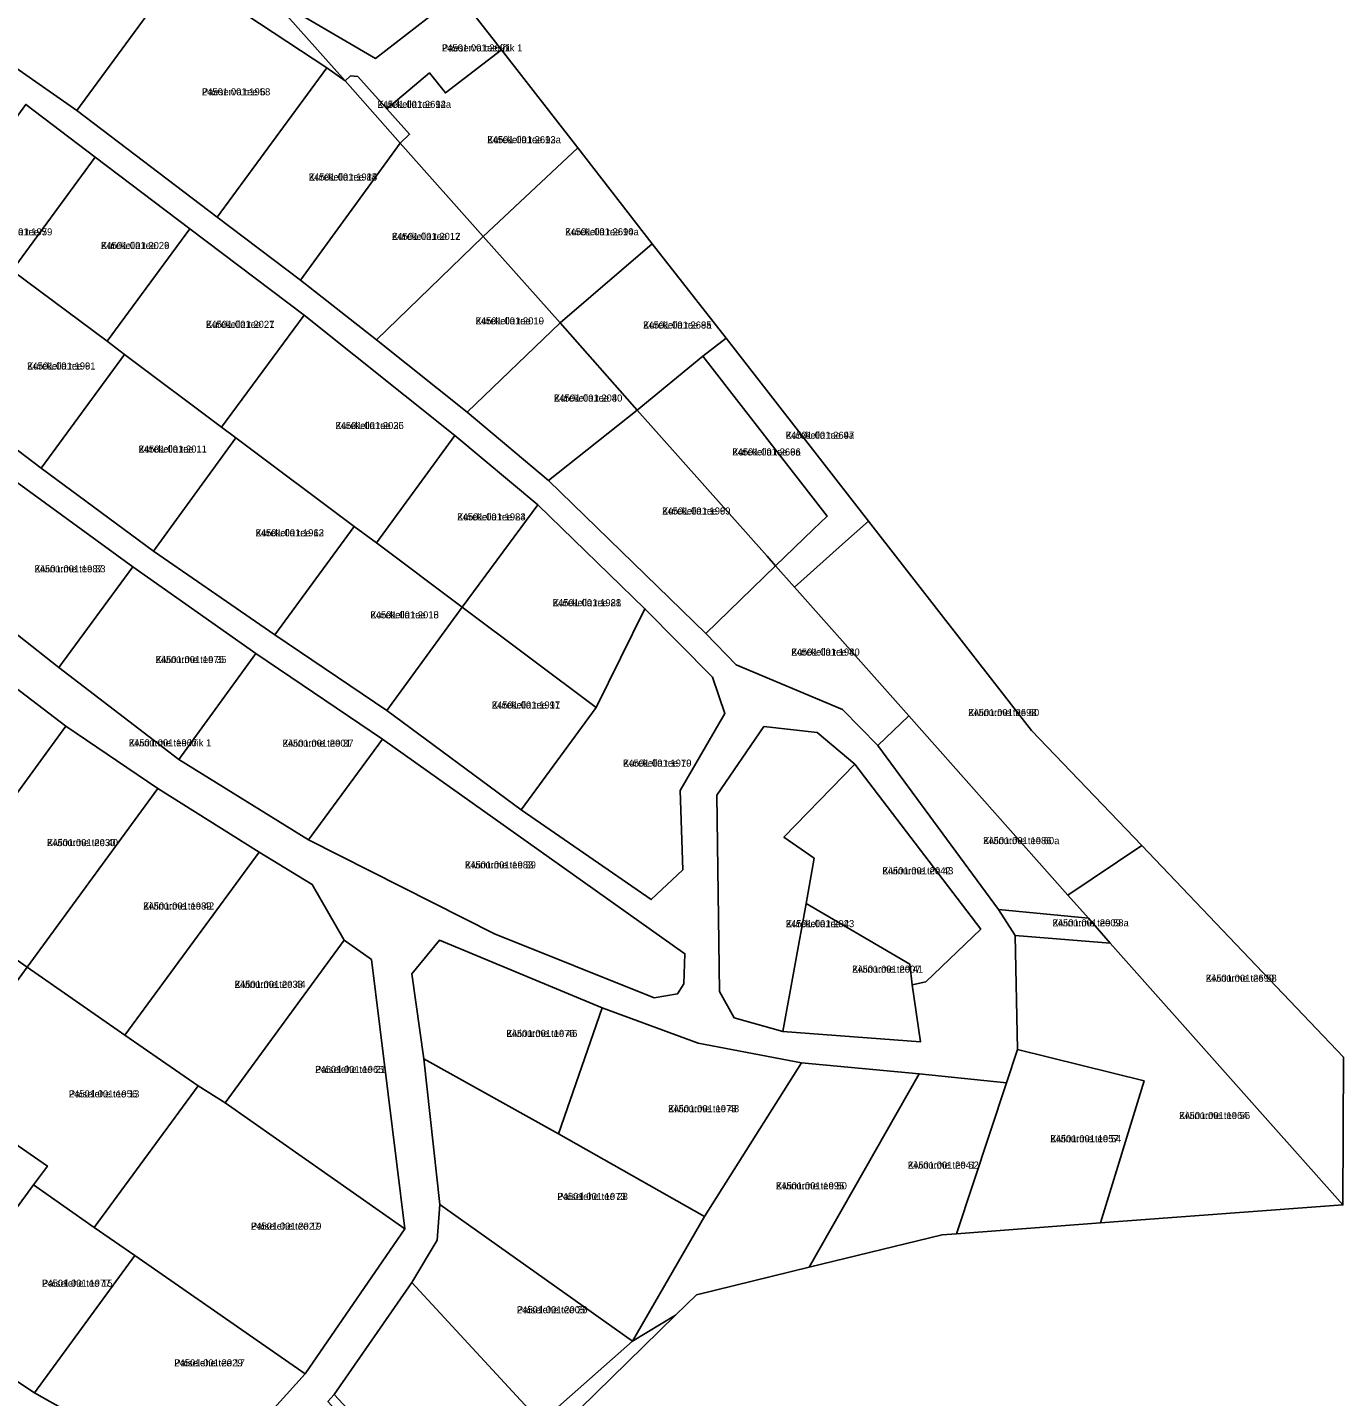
# Model space of a CAD drawing. Extents: x 551291 to 575799, y 6581704 to 6610137.
# Drawn here: x 559710.7 to 559989.7, y 6593302.2 to 6593592.3 of the extents above; entities that cross this region are included whole.
import ezdxf

# ---------------------------------------------------------------- set-up
doc = ezdxf.new("R2010")
doc.units = 0
for name, color, linetype in [('L_AADRESS', 7, 'Continuous'), ('PIIR', 7, 'Continuous'), ('TUNNUS', 7, 'Continuous')]:
    doc.layers.add(name, color=color, linetype=linetype)

msp = doc.modelspace()

# ---------------------------------------------------------------- linework, layer by layer
at = {"layer": 'PIIR'}
for points in [[(559693.82, 6593633.25), (559702.03, 6593640.34), (559704.01, 6593635.24), (559714.34, 6593627.36), (559736.46, 6593615.24), (559749.81, 6593606.84), (559762.28, 6593598.8), (559778.08, 6593580.98), (559774.19, 6593583.79), (559742.94, 6593604.41), (559719.13, 6593618), (559705.07, 6593624.88)], [(559752.19, 6593610.14), (559772.99, 6593640.46), (559802.82, 6593603.02), (559800.56, 6593601.2), (559802.05, 6593599.4), (559784.52, 6593585.74), (559762.28, 6593598.8)], [(559698.86, 6593590.33), (559719.13, 6593618), (559742.94, 6593604.41), (559721.24, 6593574.74)], [(559721.24, 6593574.74), (559742.94, 6593604.41), (559774.19, 6593583.79), (559750.95, 6593552.15)], [(559778.08, 6593580.98), (559762.28, 6593598.8), (559784.52, 6593585.74), (559802.05, 6593599.4), (559811.2, 6593587.6), (559799.32, 6593578.46), (559795.94, 6593582.69), (559786.91, 6593575.05), (559780.75, 6593581.92), (559779.19, 6593582.06)], [(559799.32, 6593578.46), (559811.2, 6593587.6), (559827.36, 6593566.82), (559807.35, 6593547.99), (559789.76, 6593567.8), (559791.74, 6593569.68), (559786.91, 6593575.05), (559795.94, 6593582.69)], [(559750.95, 6593552.15), (559774.19, 6593583.79), (559778.08, 6593580.98), (559789.76, 6593567.8), (559768.6, 6593538.79)], [(559789.76, 6593567.8), (559778.08, 6593580.98), (559779.19, 6593582.06), (559780.75, 6593581.92), (559786.91, 6593575.05), (559791.74, 6593569.68)], [(559692.59, 6593551.66), (559710.41, 6593576.02), (559725.11, 6593564.86), (559707.51, 6593540.85), (559690.02, 6593516.88), (559677.94, 6593526.12), (559695.35, 6593549.85)], [(559768.6, 6593538.79), (559789.76, 6593567.8), (559807.35, 6593547.99), (559784.72, 6593526.1)], [(559807.35, 6593547.99), (559827.36, 6593566.82), (559843.15, 6593546.45), (559823.61, 6593529.74)], [(559707.51, 6593540.85), (559725.11, 6593564.86), (559745.13, 6593549.68), (559727.67, 6593525.82)], [(559727.67, 6593525.82), (559745.13, 6593549.68), (559769.4, 6593531.36), (559751.86, 6593507.66), (559731.33, 6593523.02)], [(559784.72, 6593526.1), (559807.35, 6593547.99), (559823.61, 6593529.74), (559803.94, 6593510.82)], [(559823.61, 6593529.74), (559843.15, 6593546.45), (559858.81, 6593526.45), (559853.9, 6593522.65), (559839.98, 6593511.23)], [(559690.02, 6593516.88), (559707.51, 6593540.85), (559727.67, 6593525.82), (559731.33, 6593523.02), (559713.65, 6593498.94)], [(559751.86, 6593507.66), (559769.4, 6593531.36), (559801.34, 6593505.83), (559784.7, 6593483.1), (559780, 6593486.61), (559754.94, 6593505.35)], [(559803.94, 6593510.82), (559823.61, 6593529.74), (559839.98, 6593511.23), (559821.16, 6593496.36)], [(559853.9, 6593522.65), (559858.81, 6593526.45), (559888.95, 6593487.69), (559884.13, 6593483.38), (559873.3, 6593473.7), (559869.3, 6593478.24), (559877.27, 6593485.96), (559880.23, 6593488.78)], [(559713.65, 6593498.94), (559731.33, 6593523.02), (559751.86, 6593507.66), (559754.94, 6593505.35), (559737.43, 6593481.37)], [(559867.48, 6593480.29), (559839.98, 6593511.23), (559853.9, 6593522.65), (559880.23, 6593488.78), (559877.27, 6593485.96), (559869.3, 6593478.24)], [(559821.16, 6593496.36), (559839.98, 6593511.23), (559867.48, 6593480.29), (559869.3, 6593478.24), (559854.48, 6593463.92)], [(559737.43, 6593481.37), (559754.94, 6593505.35), (559780, 6593486.61), (559763.15, 6593463.65)], [(559784.7, 6593483.1), (559801.34, 6593505.83), (559818.92, 6593491.16), (559802.9, 6593469.48)], [(559692.15, 6593476.66), (559707.01, 6593497.03), (559733.05, 6593478.06), (559717.41, 6593456.71)], [(559802.9, 6593469.48), (559818.92, 6593491.16), (559841.61, 6593469.14), (559831.24, 6593448.22)], [(559884.13, 6593483.38), (559888.95, 6593487.69), (559923.49, 6593443.39), (559946.88, 6593418.97), (559931.22, 6593408.46), (559897.49, 6593446.47), (559873.3, 6593473.7)], [(559763.15, 6593463.65), (559780, 6593486.61), (559784.7, 6593483.1), (559802.9, 6593469.48), (559786.88, 6593447.6)], [(559717.41, 6593456.71), (559733.05, 6593478.06), (559759.13, 6593459.66), (559742.86, 6593437.25)], [(559854.48, 6593463.92), (559869.3, 6593478.24), (559873.3, 6593473.7), (559897.49, 6593446.47), (559890.93, 6593440.21), (559883.43, 6593447.81), (559860.94, 6593457.29)], [(559786.88, 6593447.6), (559802.9, 6593469.48), (559831.24, 6593448.22), (559815.38, 6593426.55)], [(559831.24, 6593448.22), (559841.61, 6593469.14), (559855.94, 6593454.68), (559858.55, 6593446.99), (559849.06, 6593430.64), (559849.63, 6593413.87), (559842.94, 6593407.53), (559815.38, 6593426.55)], [(559667.73, 6593423.01), (559696.03, 6593461.71), (559718.87, 6593444.25), (559691.39, 6593406.61), (559678.5, 6593415.53)], [(559742.86, 6593437.25), (559759.13, 6593459.66), (559785.96, 6593441.55), (559770.32, 6593420.19)], [(559691.39, 6593406.61), (559718.87, 6593444.25), (559738.39, 6593431.07), (559710.7, 6593393.19)], [(559866.82, 6593444.19), (559856.82, 6593429.67), (559857.39, 6593388.05), (559860.51, 6593382.46), (559870.85, 6593379.57), (559900.01, 6593377.42), (559898.21, 6593389.45), (559901.12, 6593390.12), (559912.75, 6593401.24), (559886.07, 6593436.22), (559878.11, 6593442.95)], [(559856.82, 6593429.67), (559866.82, 6593444.19), (559878.11, 6593442.95), (559886.07, 6593436.22), (559871.05, 6593420.79), (559877.46, 6593416.28), (559875.73, 6593406.69), (559870.85, 6593379.57), (559860.51, 6593382.46), (559857.39, 6593388.05)], [(559890.93, 6593440.21), (559897.49, 6593446.47), (559931.22, 6593408.46), (559935.59, 6593403.58), (559916.52, 6593405.43)], [(559770.32, 6593420.19), (559785.96, 6593441.55), (559850.08, 6593396.06), (559849.82, 6593389.69), (559848.53, 6593387.55), (559843.55, 6593386.73), (559809.75, 6593400.28)], [(559871.05, 6593420.79), (559886.07, 6593436.22), (559912.75, 6593401.24), (559901.12, 6593390.12), (559898.21, 6593389.45), (559897.7, 6593393.83), (559875.73, 6593406.69), (559877.46, 6593416.28)], [(559710.7, 6593393.19), (559738.39, 6593431.07), (559759.83, 6593417.58), (559731.42, 6593378.82)], [(559931.22, 6593408.46), (559946.88, 6593418.97), (559989.65, 6593374.15), (559989.5, 6593342.83), (559940.15, 6593398.29), (559935.59, 6593403.58)], [(559731.42, 6593378.82), (559759.83, 6593417.58), (559771.09, 6593410.74), (559777.86, 6593398.92), (559752.68, 6593364.47), (559746.91, 6593368.1)], [(559870.85, 6593379.57), (559875.73, 6593406.69), (559897.7, 6593393.83), (559898.21, 6593389.45), (559900.01, 6593377.42)], [(559920.07, 6593399.92), (559916.52, 6593405.43), (559935.59, 6593403.58), (559940.15, 6593398.29)], [(559752.68, 6593364.47), (559777.86, 6593398.92), (559783.63, 6593394.81), (559790.73, 6593337.77)], [(559792.23, 6593391.82), (559798.07, 6593398.94), (559832.52, 6593384.57), (559823.28, 6593357.93), (559794.74, 6593373.81)], [(559920.54, 6593375.74), (559920.07, 6593399.92), (559940.15, 6593398.29), (559989.5, 6593342.83), (559938.13, 6593339.03), (559947.38, 6593369.15)], [(559691.7, 6593367.16), (559710.7, 6593393.19), (559731.42, 6593378.82), (559746.91, 6593368.1), (559724.92, 6593338.06), (559712.01, 6593347.07), (559714.97, 6593351.07)], [(559823.28, 6593357.93), (559832.52, 6593384.57), (559852.85, 6593377.13), (559874.76, 6593372.96), (559854.24, 6593340.4)], [(559918.22, 6593368.73), (559920.54, 6593375.74), (559947.38, 6593369.15), (559938.13, 6593339.03), (559907.6, 6593336.74)], [(559798.13, 6593342.96), (559794.74, 6593373.81), (559823.28, 6593357.93), (559854.24, 6593340.4), (559838.97, 6593314)], [(559854.24, 6593340.4), (559874.76, 6593372.96), (559899.73, 6593370.6), (559876.37, 6593329.64), (559852.49, 6593323.78), (559848.07, 6593319.48), (559838.97, 6593314)], [(559876.37, 6593329.64), (559899.73, 6593370.6), (559918.22, 6593368.73), (559907.6, 6593336.74), (559904.55, 6593336.53)], [(559724.92, 6593338.06), (559746.91, 6593368.1), (559752.68, 6593364.47), (559790.73, 6593337.77), (559769.58, 6593307.09), (559733.53, 6593332.13)], [(559694.16, 6593322.68), (559712.01, 6593347.07), (559724.92, 6593338.06), (559733.53, 6593332.13), (559712.26, 6593303.04), (559695.55, 6593314.08)], [(559797.58, 6593335.39), (559798.13, 6593342.96), (559838.97, 6593314), (559819.51, 6593296.82), (559792.22, 6593326.42)], [(559712.26, 6593303.04), (559733.53, 6593332.13), (559769.58, 6593307.09), (559753.06, 6593288.74), (559743.92, 6593285.15)], [(559775.76, 6593302.69), (559792.22, 6593326.42), (559819.51, 6593296.82), (559799.96, 6593276.64)], [(559838.97, 6593314), (559848.07, 6593319.48), (559790.58, 6593263.21), (559799.56, 6593273.99), (559774.42, 6593301.19), (559775.76, 6593302.69), (559799.96, 6593276.64), (559819.51, 6593296.82)]]:
    msp.add_lwpolyline(points, close=True, dxfattribs=at)
for points in [[(559790.58, 6593263.21), (559848.07, 6593319.48), (559852.49, 6593323.78), (559876.37, 6593329.64), (559904.55, 6593336.53), (559907.6, 6593336.74), (559938.13, 6593339.03), (559989.5, 6593342.83), (559989.65, 6593374.15), (559946.88, 6593418.97), (559923.49, 6593443.39), (559888.95, 6593487.69), (559858.81, 6593526.45), (559843.15, 6593546.45), (559827.36, 6593566.82), (559811.2, 6593587.6), (559802.05, 6593599.4)], [(559698.86, 6593590.33), (559721.24, 6593574.74), (559750.95, 6593552.15), (559768.6, 6593538.79), (559784.72, 6593526.1), (559803.94, 6593510.82), (559821.16, 6593496.36), (559854.48, 6593463.92), (559860.94, 6593457.29), (559883.43, 6593447.81), (559890.93, 6593440.21), (559916.52, 6593405.43), (559920.07, 6593399.92), (559920.54, 6593375.74), (559918.22, 6593368.73), (559899.73, 6593370.6), (559874.76, 6593372.96), (559852.85, 6593377.13), (559832.52, 6593384.57), (559798.07, 6593398.94), (559792.23, 6593391.82), (559794.74, 6593373.81), (559798.13, 6593342.96), (559797.58, 6593335.39), (559792.22, 6593326.42), (559775.76, 6593302.69), (559774.42, 6593301.19)], [(559690.02, 6593516.88), (559713.65, 6593498.94), (559737.43, 6593481.37), (559763.15, 6593463.65), (559786.88, 6593447.6), (559815.38, 6593426.55), (559842.94, 6593407.53), (559849.63, 6593413.87), (559849.06, 6593430.64), (559858.55, 6593446.99), (559855.94, 6593454.68), (559841.61, 6593469.14), (559818.92, 6593491.16), (559801.34, 6593505.83), (559769.4, 6593531.36), (559745.13, 6593549.68), (559725.11, 6593564.86), (559710.41, 6593576.02)], [(559692.15, 6593476.66), (559717.41, 6593456.71), (559742.86, 6593437.25), (559770.32, 6593420.19), (559809.75, 6593400.28), (559843.55, 6593386.73), (559848.53, 6593387.55), (559849.82, 6593389.69), (559850.08, 6593396.06), (559785.96, 6593441.55), (559759.13, 6593459.66), (559733.05, 6593478.06), (559707.01, 6593497.03)], [(559753.06, 6593288.74), (559769.58, 6593307.09), (559790.73, 6593337.77), (559783.63, 6593394.81), (559777.86, 6593398.92), (559771.09, 6593410.74), (559759.83, 6593417.58), (559738.39, 6593431.07), (559718.87, 6593444.25), (559696.03, 6593461.71)], [(559691.7, 6593367.16), (559714.97, 6593351.07), (559712.01, 6593347.07), (559694.16, 6593322.68)], [(559695.55, 6593314.08), (559712.26, 6593303.04), (559743.92, 6593285.15)]]:
    msp.add_lwpolyline(points, dxfattribs=at)

# ---------------------------------------------------------------- texts
at = {"layer": 'L_AADRESS'}
for s, p in [('Paeserva tee lõik 1', (559798.57, 6593587.23)), ('Paeserva tee 6', (559747.71, 6593577.93)), ('Kurekella tee 14a', (559784.91, 6593575.28)), ('Kurekella tee 12a', (559808.18, 6593567.79)), ('Kurekella tee 14', (559770.36, 6593559.88)), ('Kurekella tee 7', (559701.52, 6593548.26)), ('Kurekella tee 12', (559787.98, 6593547.3)), ('Kurekella tee 10a', (559824.69, 6593548.28)), ('Kurekella tee 29', (559726.32, 6593545.38)), ('Kurekella tee 10', (559805.7, 6593529.4)), ('Kurekella tee 27', (559748.58, 6593528.67)), ('Kurekella tee 8a', (559841.21, 6593528.52)), ('Kurekella tee 9', (559710.68, 6593519.84)), ('Kurekella tee 8', (559822.31, 6593513.05)), ('Kurekella tee 25', (559776.01, 6593507.23)), ('Kurekella tee 4a', (559871.43, 6593505.17)), ('Kurekella tee 11', (559734.29, 6593502.24)), ('Kurekella tee 6a', (559860.1, 6593501.63)), ('Kurekella tee 6', (559845.23, 6593489.12)), ('Kurekella tee 23', (559801.81, 6593487.87)), ('Kurekella tee 13', (559759.08, 6593484.5)), ('Kivinurme tee 33', (559712.24, 6593476.87)), ('Kurekella tee 21', (559822.05, 6593469.69)), ('Kurekella tee 15', (559783.42, 6593467.11)), ('Kivinurme tee 35', (559737.89, 6593457.65)), ('Kurekella tee 4', (559872.61, 6593459.23)), ('Kurekella tee 17', (559809.14, 6593448.02)), ('Kivinurme tee 60', (559910.09, 6593446.42)), ('Kivinurme tee lõik 1', (559732.22, 6593440)), ('Kivinurme tee 37', (559764.79, 6593439.93)), ('Kurekella tee 19', (559836.96, 6593435.71)), ('Kivinurme tee 60a', (559913.26, 6593419.28)), ('Kivinurme tee 40', (559714.89, 6593418.86)), ('Kivinurme tee 39', (559803.45, 6593414.14)), ('Kivinurme tee 43', (559891.9, 6593412.9)), ('Kivinurme tee 42', (559735.27, 6593405.43)), ('Kivinurme tee 58a', (559927.95, 6593401.86)), ('Kurekella tee 2', (559871.45, 6593401.69)), ('Kivinurme tee 41', (559885.5, 6593392.06)), ('Kivinurme tee 44', (559754.64, 6593388.83)), ('Kivinurme tee 58', (559960.43, 6593390.13)), ('Kivinurme tee 46', (559812.24, 6593378.44)), ('Paiselehe tee 21', (559771.7, 6593370.81)), ('Paiselehe tee 13', (559719.51, 6593365.62)), ('Kivinurme tee 48', (559846.51, 6593362.49)), ('Kivinurme tee 56', (559954.79, 6593361.05)), ('Kivinurme tee 54', (559927.49, 6593356.13)), ('Kivinurme tee 52', (559897.29, 6593350.54)), ('Paiselehe tee 28', (559823.04, 6593343.9)), ('Kivinurme tee 50', (559869.35, 6593346.15)), ('Paiselehe tee 19', (559758.1, 6593337.6)), ('Paiselehe tee 15', (559713.84, 6593325.5)), ('Paiselehe tee 26', (559814.45, 6593319.89)), ('Paiselehe tee 17', (559741.85, 6593308.64))]:
    msp.add_text(s, height=1.5, dxfattribs=at).set_placement(p)
at = {"layer": 'TUNNUS'}
for s, p in [('24501:001:2691', (559798.57, 6593587.23)), ('24501:001:1958', (559747.71, 6593577.93)), ('24501:001:2692', (559784.91, 6593575.28)), ('24501:001:2693', (559808.18, 6593567.79)), ('24501:001:1985', (559770.36, 6593559.88)), ('24501:001:1959', (559701.52, 6593548.26)), ('24501:001:2017', (559787.98, 6593547.3)), ('24501:001:2694', (559824.69, 6593548.28)), ('24501:001:2026', (559726.32, 6593545.38)), ('24501:001:2021', (559748.58, 6593528.67)), ('24501:001:2019', (559805.7, 6593529.4)), ('24501:001:2695', (559841.21, 6593528.52)), ('24501:001:1961', (559710.68, 6593519.84)), ('24501:001:2040', (559822.31, 6593513.05)), ('24501:001:2036', (559776.01, 6593507.23)), ('24501:001:2697', (559871.43, 6593505.17)), ('24501:001:2011', (559734.29, 6593502.24)), ('24501:001:2696', (559860.1, 6593501.63)), ('24501:001:1999', (559845.23, 6593489.12)), ('24501:001:1984', (559801.81, 6593487.87)), ('24501:001:1962', (559759.08, 6593484.5)), ('24501:001:1987', (559712.24, 6593476.87)), ('24501:001:1988', (559822.05, 6593469.69)), ('24501:001:2018', (559783.42, 6593467.11)), ('24501:001:1975', (559737.89, 6593457.65)), ('24501:001:1980', (559872.61, 6593459.23)), ('24501:001:1991', (559809.14, 6593448.02)), ('24501:001:2698', (559910.09, 6593446.42)), ('24501:001:1967', (559732.22, 6593440)), ('24501:001:2001', (559764.79, 6593439.93)), ('24501:001:1970', (559836.96, 6593435.71)), ('24501:001:1986', (559913.26, 6593419.28)), ('24501:001:2030', (559714.89, 6593418.86)), ('24501:001:1983', (559803.45, 6593414.14)), ('24501:001:2042', (559891.9, 6593412.9)), ('24501:001:1989', (559735.27, 6593405.43)), ('24501:001:2009', (559927.95, 6593401.86)), ('24501:001:2043', (559871.45, 6593401.69)), ('24501:001:2007', (559885.5, 6593392.06)), ('24501:001:2038', (559754.64, 6593388.83)), ('24501:001:2699', (559960.43, 6593390.13)), ('24501:001:1976', (559812.24, 6593378.44)), ('24501:001:1965', (559771.7, 6593370.81)), ('24501:001:1956', (559719.51, 6593365.62)), ('24501:001:1978', (559846.51, 6593362.49)), ('24501:001:1964', (559954.79, 6593361.05)), ('24501:001:1957', (559927.49, 6593356.13)), ('24501:001:2041', (559897.29, 6593350.54)), ('24501:001:1973', (559823.04, 6593343.9)), ('24501:001:1995', (559869.35, 6593346.15)), ('24501:001:2027', (559758.1, 6593337.6)), ('24501:001:1977', (559713.84, 6593325.5)), ('24501:001:2005', (559814.45, 6593319.89)), ('24501:001:2029', (559741.85, 6593308.64))]:
    msp.add_text(s, height=1.5, dxfattribs=at).set_placement(p)

doc.saveas('drawing.dxf')
